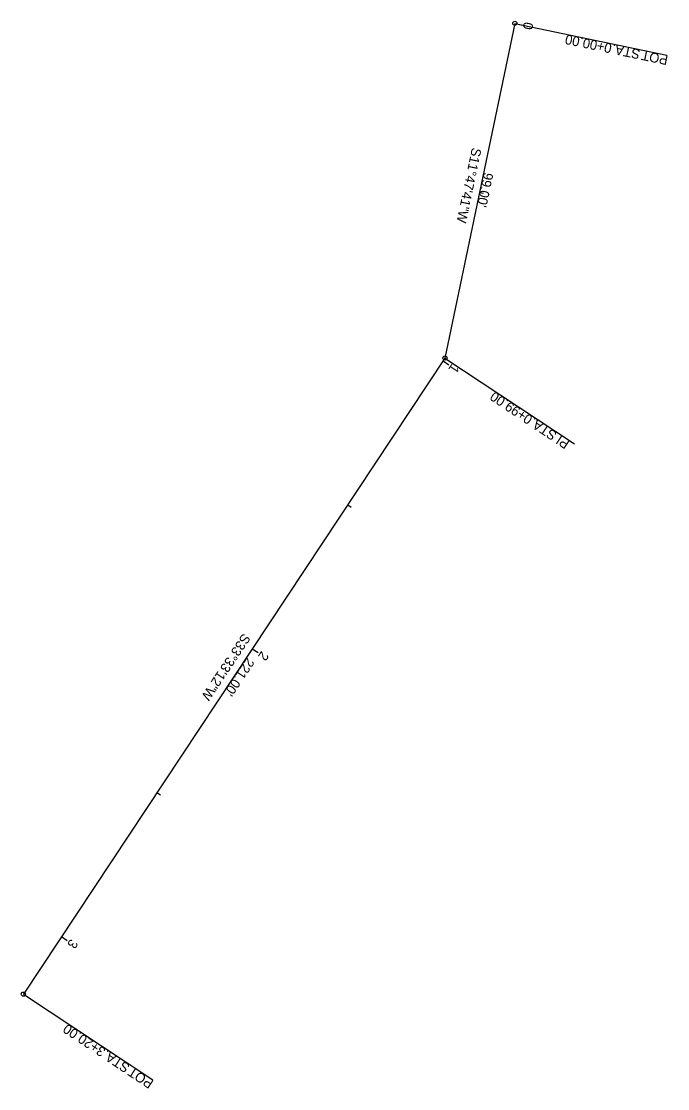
# Model space of a CAD drawing. Extents: x 2315021 to 2316490, y 701716 to 702071.
# Drawn here: x 2315020.5 to 2315207.8, y 701716.4 to 702025.5 of the extents above; entities that cross this region are included whole.
import ezdxf

# ---------------------------------------------------------------- set-up
doc = ezdxf.new("R2010")
doc.units = 0
for name, color, linetype in [('RD_X_Cells', 7, 'Continuous'), ('SV_X_Shot_Marker', 7, 'Continuous'), ('UT_X_Electric_Cells', 7, 'Continuous'), ('UT_X_Misc_Cells', 7, 'Continuous'), ('VG_X_Cells', 7, 'Continuous')]:
    doc.layers.add(name, color=color, linetype=linetype)

msp = doc.modelspace()

# ---------------------------------------------------------------- linework, layer by layer
at = {"layer": 'SV_X_Shot_Marker'}
for p, q in [((2315163.52, 702024.91), (2315207.57, 702015.71)), ((2315143.28, 701928), (2315180.78, 701903.12)), ((2315021.13, 701743.82), (2315058.63, 701718.95))]:
    msp.add_line(p, q, dxfattribs=at)
for centre in [(2315163.52, 702024.91), (2315143.28, 701928), (2315021.13, 701743.82)]:
    msp.add_circle(centre, 0.6, dxfattribs=at)
at = {"layer": 'UT_X_Electric_Cells'}
for p, q in [((2315163.52, 702024.91), (2315165.47, 702024.5)), ((2315153.3, 701975.96), (2315154.47, 701975.72)), ((2315142.73, 701927.16), (2315144.39, 701926.06)), ((2315115.09, 701885.49), (2315116.09, 701884.83)), ((2315087.46, 701843.83), (2315089.12, 701842.72)), ((2315059.82, 701802.16), (2315060.82, 701801.49)), ((2315032.19, 701760.49), (2315033.85, 701759.38))]:
    msp.add_line(p, q, dxfattribs=at)
at = {"layer": 'VG_X_Cells'}
for p, q in [((2315163.52, 702024.91), (2315143.28, 701928)), ((2315143.28, 701928), (2315021.13, 701743.82))]:
    msp.add_line(p, q, dxfattribs=at)

# ---------------------------------------------------------------- texts
at = {"layer": 'RD_X_Cells'}
for s, rotation, p in [('S11°47\'41"W', 258.2052, (2315151.13, 701989.07)), ('S33°33\'12"W', 236.4466, (2315084.78, 701848.47))]:
    msp.add_text(s, height=2.8, rotation=rotation, dxfattribs=at).set_placement(p)
at = {"layer": 'SV_X_Shot_Marker'}
for s, rotation, p in [('0+00.00', 168.2052, (2315191.81, 702018.96)), (' STA. ', 168.2052, (2315201.06, 702017.02)), ('POT', 168.2052, (2315208.11, 702015.55)), ('0+99.00', 146.4466, (2315168.94, 701910.93)), (' STA. ', 146.4466, (2315176.82, 701905.7)), ('PI', 146.4466, (2315179.64, 701903.83)), ('3+20.00', 146.4466, (2315045.2, 701727.81)), (' STA. ', 146.4466, (2315053.08, 701722.58)), ('POT', 146.4466, (2315059.08, 701718.6))]:
    msp.add_text(s, height=2.8, rotation=rotation, dxfattribs=at).set_placement(p)
at = {"layer": 'UT_X_Electric_Cells'}
for s, rotation, p in [('0', 258.2052, (2315166.19, 702025.48)), ('1', 236.4466, (2315145.32, 701926.54)), ('2', 236.4466, (2315090.12, 701843.32)), ('3', 236.4466, (2315034.84, 701759.97))]:
    msp.add_text(s, height=2.8, rotation=rotation, dxfattribs=at).set_placement(p)
at = {"layer": 'UT_X_Misc_Cells'}
for s, rotation, p in [("99.00'", 258.2052, (2315154.58, 701981.89)), ("221.00'", 236.4466, (2315085.93, 701841.45))]:
    msp.add_text(s, height=2.8, rotation=rotation, dxfattribs=at).set_placement(p)

doc.saveas('drawing.dxf')
